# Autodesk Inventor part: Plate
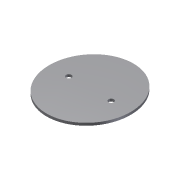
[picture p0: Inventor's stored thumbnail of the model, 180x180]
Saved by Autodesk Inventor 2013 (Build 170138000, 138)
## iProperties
Created: 2009-04
Part Number: Plate
Document SubType Name: Modeling
Designer: Sham
Density: 1 g/cm^3
Material: Generic
Author: Sham
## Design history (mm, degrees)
sketch "Sketch1"
  geometry: C1 r 6.25 at (-50, 0); C2 r 6.25 at (50, 0); 4 further points; 1 other entity
  constraints: 2 centre point, 1 coincident, 5 other
  dimensions: "d1" = 12.5 diameter of C1; "d2" = 12.5 diameter of C2; "d3" = 100 distance of C2.centre C1.centre; "d4" = 102.5 distance of point (0, 0) point (0, 102.5); "d5" = 96 distance of point (0, 0) point (-96, 0); "d6" = 50 distance of point (0, 0) C1.centre
extrude "Extrusion1" new body sketch "Sketch1" distance "d7" = 6; taper "d8" = 0 deg
body "Solid1"
